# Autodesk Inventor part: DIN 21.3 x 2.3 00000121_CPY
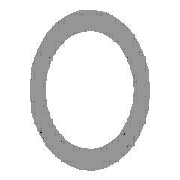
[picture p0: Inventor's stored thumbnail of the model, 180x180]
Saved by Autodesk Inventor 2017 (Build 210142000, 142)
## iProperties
Created: 2017-11
Part Number: DIN 21.3 x 2.3 00000121_CPY
Material: Steel, Mild
Description: Pipe
Document SubType Name: Modeling
Standard: DIN
Designer: iusti
Standard Revision: 2006-07
Standards Organization: DIN
Language: en-US
Size Designation: 21.3 x 2.3
Categories: <MemberInstance><Categories><Category DisplayName="Structural Shapes" InternalName="089c4875-fa83-4c05-b084-43b9cc11f5ed" Mnemonic="GRDR"><CategoryParameter Dis
Stock Number: 21.3 x 2.3
Density: 7.85 g/cm^3
Appearance: Semi-Polished
_CCFamilyMember: 1
_CCFamilyDisplayName: DIN EN 10210-2 - Pipe
_FrameMemberDoc: Frame Member File
_Version: 15.0.0
_GetPNFromCC: 1
IsCustomPart: 1
Author: iusti
G_L: 5240.313 mm
G_W: 21.300 mm
G_H: 21.300 mm
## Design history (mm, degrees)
node "Start plane"
node "End plane"
sketch "Sketch"
  geometry: C1 r 8.35 at (0, 0); C2 r 10.65 at (0, 0); 2 further points
  constraints: 3 coincident, 2 centre point
  dimensions: "d0" = 21.3 diameter of C2 (= G_H); "d1" = 2.3 radial gap between concentric circles of C2 C1 (= G_T)
extrude "Body" new body sketch "Sketch" stored distance "d2" = 5240.31264 (= G_L); taper "d3" = 0 deg
node "Driven Length"
  sketch "Sketch3"
    geometry: L1 (0, 0)-(10, 0) reference
    constraints: 2 end point, 1 horizontal
  workplane "Work Plane3"
  sketch "Sketch4"
    geometry: L1 (-2, 0)-(12, 0) reference; L2 (-2, 5240.313)-(12, 5240.313) reference
    dimensions: "d7" = 5240.31264 distance between parallel lines of L1 L2 (derived)
body "Solid1"
other parameters: "G_H" = 21.3 [user parameter; used in 1 equation term], "G_T" = 2.3 [user parameter; used in 1 equation term], "G_L" = 5240.31264 (= d7) [user parameter; used in 1 equation term], "G_OFFSET_START" = 0 [user parameter; used in 1 equation term], "G_OFFSET_END" = 0 [user parameter; used in 1 equation term], "d4" = 0 (computed from G_OFFSET_START), "d5" = 5240.31264 (= G_OFFSET_END + B_L), "B_L" = 5240.31264 [user parameter; used in 1 equation term], "d6" = 90 deg
